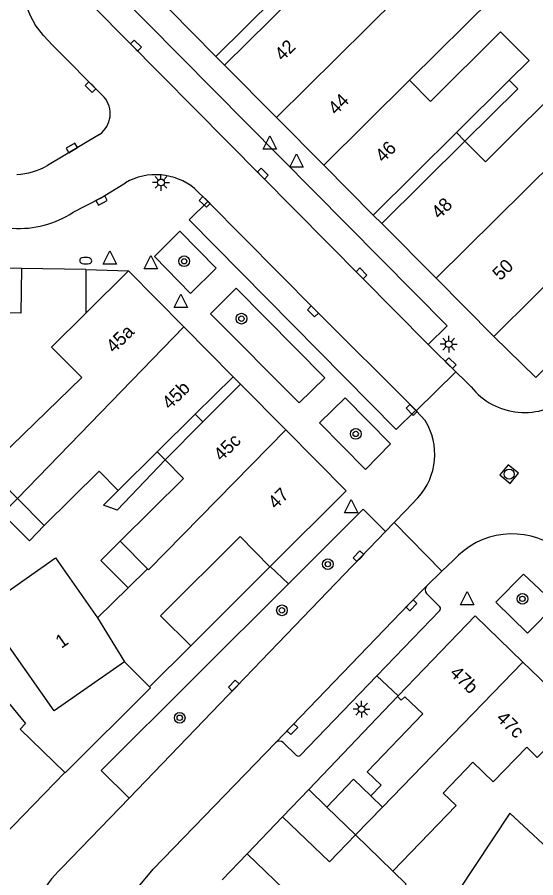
# Model space of a CAD drawing. Extents: x 132573 to 132944, y 398226 to 398676.
# Drawn here: x 132822.1 to 132860.9, y 398438.1 to 398502.5 of the extents above; entities that cross this region are included whole.
import ezdxf

# ---------------------------------------------------------------- set-up
doc = ezdxf.new("R2010")
doc.units = 0
for name, color, linetype in [('gg-afsc-erfafscheiding', 7, 'Continuous'), ('gg-afsc-muur', 7, 'Continuous'), ('gg-anno-huisnummerreeks BGT', 7, 'Continuous'), ('gg-bbg-gedigitaliseerde bebouwing', 7, 'Continuous'), ('gg-bbg-gedigitaliseerde bebouwing onder overbouw', 7, 'Continuous'), ('gg-bbg-gedigitaliseerde bijgebouw', 7, 'Continuous'), ('gg-bbg-gedigitaliseerde overbouw', 7, 'Continuous'), ('gg-bbg-hoofdgebouw', 7, 'Continuous'), ('gg-bbg-luifel en loopbrug', 7, 'Continuous'), ('gg-bbg-onder overbouw', 7, 'Continuous'), ('gg-bbg-pand overbouw', 7, 'Continuous'), ('gg-bbg-tussenscheiding', 7, 'Continuous'), ('gg-bbg-tussenscheiding niveau 01', 7, 'Continuous'), ('gg-knt-verharding', 7, 'Continuous'), ('gg-knt-verharding nz', 7, 'Continuous'), ('gt-symb-boom', 7, 'Continuous'), ('gt-symb-brandkraan', 7, 'Continuous'), ('gt-symb-kolk', 7, 'Continuous'), ('gt-symb-lichtmast', 7, 'Continuous'), ('gt-symb-rioolschacht', 7, 'Continuous'), ('gt-symb-waterafsluiter', 7, 'Continuous')]:
    doc.layers.add(name, color=color, linetype=linetype)

msp = doc.modelspace()

# ---------------------------------------------------------------- linework, layer by layer
at = {"layer": 'gg-afsc-erfafscheiding'}
msp.add_line((132829.679, 398467.047), (132828.579, 398465.958), dxfattribs=at)
for points in [[(132855.615, 398493.198), (132859.572, 398497.123), (132858.936, 398497.764)], [(132833.196, 398469.351), (132829.602, 398465.59), (132828.579, 398465.958)]]:
    msp.add_lwpolyline(points, dxfattribs=at)
at = {"layer": 'gg-afsc-muur'}
for p, q in [((132827.272, 398483.597), (132822.457, 398483.665)), ((132841.023, 398461.333), (132835.12, 398455.43)), ((132843.945, 398444.661), (132850.57, 398451.63))]:
    msp.add_line(p, q, dxfattribs=at)
at = {"layer": 'gg-bbg-gedigitaliseerde bebouwing'}
for p, q in [((132857.824, 398504.05), (132851.47, 398497.765)), ((132858.936, 398497.764), (132854.98, 398493.837)), ((132829.679, 398467.047), (132832.605, 398469.946)), ((132833.196, 398469.351), (132834.576, 398467.958)), ((132829.831, 398463.255), (132834.576, 398467.958)), ((132828.142, 398457.511), (132830.421, 398459.769)), ((132843.945, 398444.661), (132845.299, 398443.343)), ((132848.57, 398444.2), (132849.444, 398443.35)), ((132845.299, 398443.343), (132847.43, 398441.27)), ((132849.444, 398443.35), (132847.43, 398441.27))]:
    msp.add_line(p, q, dxfattribs=at)
for points in [[(132851.47, 398497.765), (132853.045, 398496.178), (132858.286, 398501.379), (132860.416, 398499.233), (132858.936, 398497.764)], [(132855.615, 398493.198), (132857.149, 398491.652), (132863.798, 398498.252)], [(132822.151, 398466.45), (132819.925, 398468.698), (132826.95, 398475.5)], [(132824.153, 398464.429), (132828.251, 398468.489), (132829.679, 398467.047)], [(132821.712, 398459.704), (132824.986, 398462.002), (132828.142, 398457.511)], [(132853.984, 398444.409), (132856.211, 398446.712), (132857.728, 398445.246), (132860.236, 398447.842), (132861.028, 398447.078), (132862.909, 398449.025)], [(132850.217, 398438.558), (132854.962, 398443.464), (132853.984, 398444.409)], [(132865.947, 398442.685), (132862.841, 398439.321), (132858.972, 398442.892), (132853.795, 398435.076), (132852.967, 398434.14)], [(132850.217, 398438.558), (132851.224, 398437.577), (132848.049, 398434.231)]]:
    msp.add_lwpolyline(points, dxfattribs=at)
at = {"layer": 'gg-bbg-gedigitaliseerde bebouwing onder overbouw'}
for p, q in [((132836.992, 398499.53), (132843.335, 398505.824)), ((132837.639, 398498.878), (132843.982, 398505.172)), ((132848.763, 398487.668), (132854.98, 398493.837)), ((132849.397, 398487.029), (132855.615, 398493.198)), ((132838.29, 398475.569), (132835.448, 398472.758)), ((132838.835, 398475.018), (132836.015, 398472.184)), ((132835.448, 398472.758), (132832.605, 398469.946)), ((132836.015, 398472.184), (132833.196, 398469.351))]:
    msp.add_line(p, q, dxfattribs=at)
at = {"layer": 'gg-bbg-gedigitaliseerde bijgebouw'}
for points in [[(132822.151, 398466.45), (132821.034, 398465.295), (132823.036, 398463.274), (132824.153, 398464.429)], [(132830.421, 398459.769), (132828.386, 398461.823), (132829.831, 398463.255)]]:
    msp.add_lwpolyline(points, dxfattribs=at)
at = {"layer": 'gg-bbg-gedigitaliseerde overbouw'}
for p, q in [((132854.98, 398493.837), (132855.615, 398493.198)), ((132832.605, 398469.946), (132833.196, 398469.351))]:
    msp.add_line(p, q, dxfattribs=at)
at = {"layer": 'gg-bbg-hoofdgebouw'}
for p, q in [((132833.506, 398503.044), (132836.992, 398499.53)), ((132837.639, 398498.878), (132841.529, 398494.958)), ((132845.056, 398491.403), (132841.529, 398494.958)), ((132845.056, 398491.403), (132848.763, 398487.668)), ((132849.397, 398487.029), (132853.457, 398482.937)), ((132830.448, 398483.491), (132827.256, 398480.328)), ((132830.448, 398483.491), (132834.587, 398479.31)), ((132853.457, 398482.937), (132857.78, 398478.58)), ((132827.256, 398480.328), (132824.688, 398477.784)), ((132838.29, 398475.569), (132834.587, 398479.31)), ((132824.688, 398477.784), (132826.95, 398475.5)), ((132842.227, 398471.59), (132838.835, 398475.018)), ((132846.74, 398467.03), (132842.227, 398471.59)), ((132841.055, 398461.365), (132846.74, 398467.03)), ((132841.023, 398461.333), (132841.055, 398461.365)), ((132850.611, 398451.673), (132856.38, 398457.67)), ((132856.38, 398457.67), (132859.956, 398454.208)), ((132832.02, 398452.35), (132835.12, 398455.43)), ((132832.02, 398452.35), (132830.14, 398454.22)), ((132863.28, 398450.99), (132859.956, 398454.208)), ((132850.611, 398451.673), (132850.57, 398451.63)), ((132843.945, 398444.661), (132841.981, 398442.626)), ((132841.981, 398442.626), (132839.317, 398439.866))]:
    msp.add_line(p, q, dxfattribs=at)
for points in [[(132857.78, 398478.58), (132863.91, 398484.66), (132862.01, 398486.57), (132868.753, 398493.263)], [(132835.12, 398455.43), (132832.855, 398457.665), (132838.796, 398463.608), (132841.023, 398461.333)], [(132830.14, 398454.22), (132824.9, 398450.55), (132819.54, 398458.18), (132821.712, 398459.704)], [(132850.57, 398451.63), (132850.85, 398451.35), (132851.12, 398451.62), (132852.47, 398450.33), (132848.31, 398446), (132849.34, 398445), (132848.57, 398444.2)]]:
    msp.add_lwpolyline(points, dxfattribs=at)
at = {"layer": 'gg-bbg-luifel en loopbrug'}
for p, q in [((132822.457, 398483.665), (132817.28, 398483.74)), ((132827.272, 398483.597), (132827.256, 398480.328)), ((132827.272, 398483.597), (132830.448, 398483.491))]:
    msp.add_line(p, q, dxfattribs=at)
for points in [[(132822.457, 398483.665), (132822.408, 398480.315), (132817.188, 398480.392)], [(132848.57, 398444.2), (132847.294, 398445.441), (132845.299, 398443.343)]]:
    msp.add_lwpolyline(points, dxfattribs=at)
at = {"layer": 'gg-bbg-onder overbouw'}
msp.add_line((132846.034, 398433.434), (132839.317, 398439.866), dxfattribs=at)
at = {"layer": 'gg-bbg-pand overbouw'}
for p, q in [((132836.992, 398499.53), (132837.639, 398498.878)), ((132848.763, 398487.668), (132849.397, 398487.029)), ((132838.29, 398475.569), (132838.835, 398475.018)), ((132839.317, 398439.866), (132837.455, 398437.904))]:
    msp.add_line(p, q, dxfattribs=at)
at = {"layer": 'gg-bbg-tussenscheiding'}
for p, q in [((132841.529, 398494.958), (132854.288, 398507.624)), ((132851.47, 398497.765), (132845.056, 398491.403)), ((132866.33, 398495.702), (132853.457, 398482.937)), ((132834.587, 398479.31), (132822.151, 398466.45)), ((132822.151, 398466.45), (132824.153, 398464.429)), ((132831.866, 398461.201), (132829.831, 398463.255)), ((132830.421, 398459.769), (132831.866, 398461.201)), ((132828.142, 398457.511), (132830.14, 398454.22)), ((132849.444, 398443.35), (132859.956, 398454.208)), ((132847.43, 398441.27), (132850.217, 398438.558))]:
    msp.add_line(p, q, dxfattribs=at)
for points in [[(132842.227, 398471.59), (132831.953, 398461.113), (132831.866, 398461.201)], [(132841.981, 398442.626), (132845.493, 398439.269), (132847.43, 398441.27)]]:
    msp.add_lwpolyline(points, dxfattribs=at)
at = {"layer": 'gg-bbg-tussenscheiding niveau 01'}
msp.add_line((132835.448, 398472.758), (132836.015, 398472.184), dxfattribs=at)
at = {"layer": 'gg-knt-verharding'}
for p, q in [((132852.879, 398477.985), (132827.875, 398503.225)), ((132828.292, 398493.708), (132824.38, 398491.379)), ((132835.393, 398489.657), (132836.394, 398488.69)), ((132854.93, 398475.936), (132852.879, 398477.985)), ((132851.969, 398473.025), (132854.93, 398475.936)), ((132855.677, 398475.208), (132854.93, 398475.936)), ((132851.941, 398473.053), (132851.969, 398473.025)), ((132851.969, 398473.025), (132852.633, 398472.3)), ((132848.015, 398465.643), (132842.415, 398460.056)), ((132849.684, 398463.971), (132848.015, 398465.643)), ((132851.191, 398465.546), (132850.335, 398464.652)), ((132850.335, 398464.652), (132849.684, 398463.971)), ((132853.902, 398461.008), (132850.335, 398464.652)), ((132849.684, 398463.971), (132830.491, 398444.031)), ((132853.902, 398461.008), (132854.764, 398461.839)), ((132842.415, 398460.056), (132841.055, 398461.365)), ((132852.741, 398459.889), (132853.902, 398461.008)), ((132853.741, 398458.337), (132852.741, 398459.332)), ((132849.016, 398453.17), (132853.74, 398458.079)), ((132843.3, 398447.229), (132849.016, 398453.17)), ((132850.611, 398451.673), (132849.016, 398453.17)), ((132842.024, 398448.179), (132843.023, 398447.229)), ((132821.039, 398441.152), (132825.68, 398445.95)), ((132830.491, 398444.031), (132825.473, 398438.822))]:
    msp.add_line(p, q, dxfattribs=at)
for points in [[(132828.623, 398496.497), (132824.777, 398500.372), (132824.102, 398501.116), (132823.479, 398501.906)], [(132826.308, 398487.883), (132828.346, 398488.935), (132830.222, 398490.082)], [(132836.394, 398488.69), (132844.391, 398480.597), (132851.941, 398473.053)], [(132834.302, 398486.463), (132832.387, 398484.561), (132835.08, 398481.806), (132837.011, 398483.697), (132834.302, 398486.463)], [(132838.512, 398482.193), (132836.597, 398480.282), (132843.227, 398473.607), (132845.13, 398475.483), (132838.512, 398482.193)], [(132857.78, 398478.58), (132860.91, 398475.497), (132862.552, 398477.162)], [(132846.652, 398473.994), (132844.738, 398472.118), (132848.172, 398468.616), (132850.041, 398470.536), (132846.652, 398473.994)], [(132821.14, 398460.29), (132817.06, 398456.49), (132822.75, 398449.61)], [(132860.299, 398456.375), (132862.406, 398458.53), (132859.999, 398460.795), (132857.937, 398458.694), (132860.299, 398456.375)], [(132842.415, 398460.056), (132828.414, 398446.088), (132830.491, 398444.031)], [(132825.68, 398445.95), (132825.716, 398445.915), (132832.097, 398452.271), (132832.02, 398452.35)], [(132825.68, 398445.95), (132822.338, 398449.184), (132822.75, 398449.61)], [(132830.702, 398436.785), (132832.286, 398438.714), (132841.442, 398448.172)]]:
    msp.add_lwpolyline(points, dxfattribs=at)
for centre, radius, start, end in [((132831.859, 398506.802), 9.706, 137.469, 210.2954), ((132827.174, 398495.255), 1.908, 305.8523, 40.61123), ((132821.858, 398495.754), 5.05, 272.79508, 299.96492), ((132832.498, 398486.099), 4.587, 50.85933, 119.74361), ((132822.294, 398493.902), 7.235, 265.78178, 303.6979), ((132853.097, 398459.611), 0.452, 141.95893, 218.04107), ((132853.597, 398458.209), 0.193, 317.78848, 41.76737), ((132841.737, 398447.856), 0.433, 48.40261, 132.97557), ((132843.162, 398447.359), 0.19, 223.14276, 316.85724), ((132833.836, 398430.429), 11.849, 134.89737, 149.6532)]:
    msp.add_arc(centre, radius, start, end, dxfattribs=at)
at = {"layer": 'gg-knt-verharding nz'}
for p, q in [((132856.085, 398474.802), (132855.677, 398475.208)), ((132852.101, 398466.513), (132851.191, 398465.546)), ((132854.764, 398461.839), (132855.141, 398462.202))]:
    msp.add_line(p, q, dxfattribs=at)
for points in [[(132852.879, 398477.985), (132854.282, 398479.381), (132829.326, 398504.618), (132827.875, 398503.225)], [(132836.394, 398488.69), (132834.979, 398487.302), (132850.475, 398471.615), (132851.941, 398473.053)], [(132852.741, 398459.889), (132851.475, 398458.599), (132841.442, 398448.172)]]:
    msp.add_lwpolyline(points, dxfattribs=at)
for centre, radius, start, end in [((132860.082, 398478.019), 5.131, 218.82478, 310.59907), ((132848.542, 398469.758), 4.816, 317.63886, 31.85624), ((132859.156, 398457.971), 5.833, 49.56638, 133.50414)]:
    msp.add_arc(centre, radius, start, end, dxfattribs=at)
at = {"layer": 'gt-symb-boom'}
for centre, radius in [((132834.617, 398484.211), 0.4), ((132834.617, 398484.211), 0.2), ((132838.898, 398479.913), 0.4), ((132838.898, 398479.913), 0.2), ((132847.452, 398471.288), 0.4), ((132847.452, 398471.288), 0.2), ((132845.364, 398461.541), 0.4), ((132845.364, 398461.541), 0.2), ((132859.92, 398458.943), 0.4), ((132859.92, 398458.943), 0.2), ((132841.93, 398458.083), 0.4), ((132841.93, 398458.083), 0.2), ((132834.28, 398450.041), 0.4), ((132834.28, 398450.041), 0.2)]:
    msp.add_circle(centre, radius, dxfattribs=at)
at = {"layer": 'gt-symb-brandkraan'}
for centre, radius, start, end in [((132827.008, 398484.26), 0.206, 106.13847, 251.00461), ((132827.917, 398486.902), 3, 251.00461, 251.6795), ((132827.785, 398481.576), 3, 105.46358, 106.13847), ((132827.269, 398484.944), 0.938, 251.6795, 285.4636), ((132827.235, 398483.564), 0.938, 71.67952, 105.46358), ((132826.719, 398486.932), 3, 285.4636, 286.13849), ((132826.587, 398481.606), 3, 71.00462, 71.67952), ((132827.496, 398484.248), 0.206, 286.13849, 71.00462)]:
    msp.add_arc(centre, radius, start, end, dxfattribs=at)
at = {"layer": 'gt-symb-kolk'}
for points in [[(132830.866, 398500.209), (132831.13, 398499.943), (132831.414, 398500.224), (132830.886, 398500.757), (132830.602, 398500.475), (132830.866, 398500.209)], [(132827.758, 398497.382), (132827.496, 398497.65), (132827.21, 398497.371), (132827.734, 398496.834), (132828.02, 398497.114), (132827.758, 398497.382)], [(132826.313, 398492.52), (132826.635, 398492.713), (132826.429, 398493.056), (132825.786, 398492.67), (132825.991, 398492.327), (132826.313, 398492.52)], [(132840.361, 398490.628), (132840.625, 398490.361), (132840.909, 398490.642), (132840.382, 398491.176), (132840.097, 398490.895), (132840.361, 398490.628)], [(132828.346, 398488.935), (132828.014, 398488.76), (132828.201, 398488.406), (132828.864, 398488.756), (132828.678, 398489.11), (132828.346, 398488.935)], [(132836.29, 398488.795), (132836.02, 398489.055), (132835.742, 398488.766), (132836.283, 398488.247), (132836.56, 398488.535), (132836.29, 398488.795)], [(132847.741, 398483.159), (132848.005, 398482.893), (132848.289, 398483.175), (132847.761, 398483.707), (132847.477, 398483.425), (132847.741, 398483.159)], [(132844.391, 398480.597), (132844.127, 398480.864), (132843.843, 398480.583), (132844.37, 398480.049), (132844.655, 398480.33), (132844.391, 398480.597)], [(132854.413, 398476.44), (132854.682, 398476.178), (132854.961, 398476.465), (132854.424, 398476.988), (132854.144, 398476.702), (132854.413, 398476.44)], [(132851.771, 398473.223), (132851.506, 398473.488), (132851.223, 398473.205), (132851.754, 398472.675), (132852.036, 398472.958), (132851.771, 398473.223)], [(132847.797, 398461.999), (132848.056, 398462.27), (132847.767, 398462.546), (132847.249, 398462.005), (132847.538, 398461.728), (132847.797, 398461.999)], [(132851.475, 398458.599), (132851.212, 398458.331), (132851.498, 398458.051), (132852.023, 398458.587), (132851.738, 398458.867), (132851.475, 398458.599)], [(132838.468, 398452.313), (132838.729, 398452.582), (132838.442, 398452.861), (132837.92, 398452.322), (132838.207, 398452.044), (132838.468, 398452.313)], [(132842.559, 398449.33), (132842.299, 398449.06), (132842.587, 398448.782), (132843.107, 398449.323), (132842.819, 398449.6), (132842.559, 398449.33)]]:
    msp.add_lwpolyline(points, dxfattribs=at)
at = {"layer": 'gt-symb-lichtmast'}
for p, q in [((132832.705, 398490.29), (132832.44, 398490.555)), ((132832.882, 398490.363), (132832.882, 398490.738)), ((132833.059, 398490.29), (132833.324, 398490.555)), ((132832.632, 398490.113), (132832.257, 398490.113)), ((132832.705, 398489.936), (132832.44, 398489.671)), ((132832.882, 398489.863), (132832.882, 398489.488)), ((132833.324, 398489.671), (132833.059, 398489.936)), ((132833.132, 398490.113), (132833.507, 398490.113)), ((132854.225, 398478.18), (132853.96, 398478.445)), ((132854.402, 398478.253), (132854.402, 398478.628)), ((132854.579, 398478.18), (132854.844, 398478.445)), ((132854.152, 398478.003), (132853.777, 398478.003)), ((132854.225, 398477.826), (132853.96, 398477.561)), ((132854.402, 398477.753), (132854.402, 398477.378)), ((132854.844, 398477.561), (132854.579, 398477.826)), ((132854.652, 398478.003), (132855.027, 398478.003)), ((132847.888, 398450.932), (132847.888, 398451.307)), ((132847.638, 398450.682), (132847.263, 398450.682)), ((132847.711, 398450.859), (132847.446, 398451.124)), ((132848.065, 398450.859), (132848.33, 398451.124)), ((132848.138, 398450.682), (132848.513, 398450.682)), ((132847.711, 398450.505), (132847.446, 398450.24)), ((132847.888, 398450.432), (132847.888, 398450.057)), ((132848.33, 398450.24), (132848.065, 398450.505))]:
    msp.add_line(p, q, dxfattribs=at)
for centre in [(132832.882, 398490.113), (132854.402, 398478.003), (132847.888, 398450.682)]:
    msp.add_circle(centre, 0.25, dxfattribs=at)
at = {"layer": 'gt-symb-rioolschacht'}
msp.add_lwpolyline([(132858.223, 398468.215), (132858.991, 398467.575), (132859.631, 398468.343), (132858.863, 398468.983)], close=True, dxfattribs=at)
msp.add_circle((132858.927, 398468.279), 0.375, dxfattribs=at)
at = {"layer": 'gt-symb-waterafsluiter'}
for p, q in [((132840.53, 398492.601), (132841.03, 398493.601)), ((132841.03, 398493.601), (132841.53, 398492.601)), ((132841.53, 398492.601), (132840.53, 398492.601)), ((132842.512, 398491.246), (132843.012, 398492.246)), ((132843.012, 398492.246), (132843.512, 398491.246)), ((132843.512, 398491.246), (132842.512, 398491.246)), ((132828.562, 398483.982), (132829.062, 398484.982)), ((132829.062, 398484.982), (132829.562, 398483.982)), ((132831.617, 398483.641), (132832.117, 398484.641)), ((132832.117, 398484.641), (132832.617, 398483.641)), ((132829.562, 398483.982), (132828.562, 398483.982)), ((132832.617, 398483.641), (132831.617, 398483.641)), ((132833.861, 398480.745), (132834.361, 398481.745)), ((132834.361, 398481.745), (132834.861, 398480.745)), ((132834.861, 398480.745), (132833.861, 398480.745)), ((132846.617, 398465.368), (132847.117, 398466.368)), ((132847.117, 398466.368), (132847.617, 398465.368)), ((132847.617, 398465.368), (132846.617, 398465.368)), ((132855.277, 398458.488), (132855.777, 398459.488)), ((132855.777, 398459.488), (132856.277, 398458.488)), ((132856.277, 398458.488), (132855.277, 398458.488))]:
    msp.add_line(p, q, dxfattribs=at)

# ---------------------------------------------------------------- texts
at = {"layer": 'gg-anno-huisnummerreeks BGT'}
for s, rotation, p in [('42', 44.8, (132841.978, 398499.134)), ('44', 44.8, (132845.97, 398495.107)), ('46', 44.8, (132849.501, 398491.545)), ('48', 44.8, (132853.702, 398487.31)), ('50', 44.8, (132858.271, 398482.709)), ('45a', 44.7, (132829.366, 398477.285)), ('45b', 44.7, (132833.549, 398473.057)), ('45c', 44.7, (132837.408, 398469.18)), ('47', 44.7, (132841.478, 398465.6)), ('1', 35, (132825.435, 398455.199)), ('47b', 315.9, (132854.414, 398453.311)), ('47c', 315.9, (132857.904, 398449.932))]:
    msp.add_text(s, height=1, rotation=rotation, dxfattribs=at).set_placement(p)

doc.saveas('drawing.dxf')
